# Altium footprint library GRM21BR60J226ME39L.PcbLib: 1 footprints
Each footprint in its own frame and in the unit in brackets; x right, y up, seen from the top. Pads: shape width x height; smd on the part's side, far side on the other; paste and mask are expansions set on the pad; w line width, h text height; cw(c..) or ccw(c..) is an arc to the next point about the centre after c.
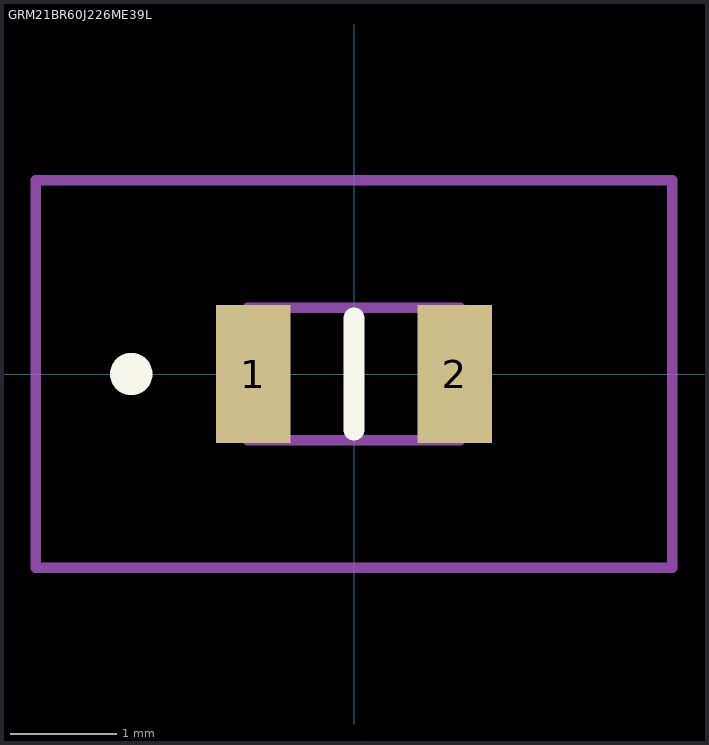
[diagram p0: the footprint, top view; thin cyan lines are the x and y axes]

## GRM21BR60J226ME39L [mm]
pads (2):
  rect 0.7x1.3 smd: 1(-0.95,0) 2(0.95,0)
Top Overlay:
  lines w0.2: 0,-0.525 0,0.525 ; -2.1,-0.1 cw(c-2.1,0) -2.1,0.1 ; -2.1,-0.1 -2.1,-0.1 ; -2.1,-0.1 ccw(c-2.1,0) -2.1,0.1 ; -2.1,0.1 -2.1,0.1
Mechanical 15:
  lines w0.1: -1,-0.625 1,-0.625 1,0.625 -1,0.625 -1,-0.625
Mechanical 20:
  lines w0.1: -3,-1.825 3,-1.825 3,1.825 -3,1.825 -3,-1.825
